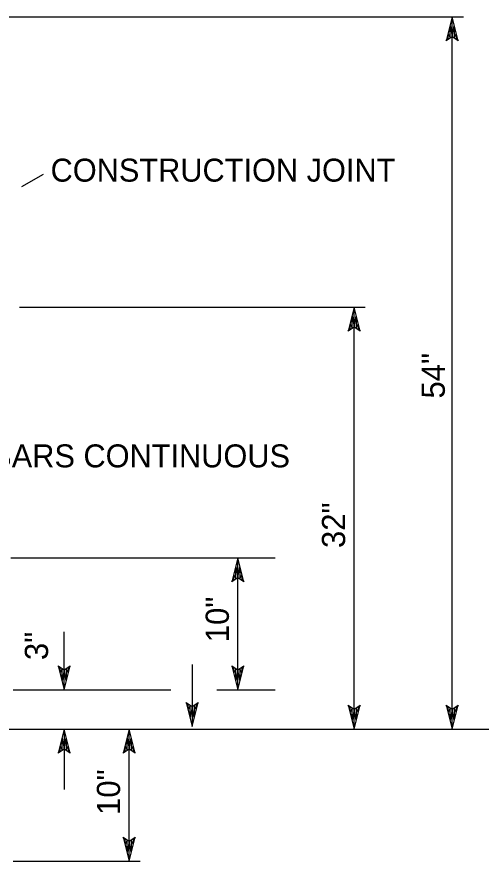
# Model space of a CAD drawing. Extents: x 504255 to 505955, y 659986 to 661086.
# Drawn here: x 504576.9 to 504692.9, y 660124.5 to 660335.2 of the extents above; entities that cross this region are included whole.
import ezdxf

# ---------------------------------------------------------------- set-up
doc = ezdxf.new("R2010")
doc.units = 0
doc.layers.add('Level1', color=7, linetype='Continuous')
doc.layers.add('Level63', color=7, linetype='Continuous')

msp = doc.modelspace()

# ---------------------------------------------------------------- linework, layer by layer
at = {"layer": 'Level1'}
for p, q in [((504537.11, 660335.21), (504688.45, 660335.21)), ((504685.66, 660157.45), (504685.66, 660335.21)), ((504578.14, 660292.9), (504583.59, 660296)), ((504577.6, 660262.79), (504663.96, 660262.79)), ((504661.17, 660157.45), (504661.17, 660262.79)), ((504575.42, 660200.24), (504641.43, 660200.24)), ((504632.14, 660167.32), (504632.14, 660200.24)), ((504588.77, 660167.32), (504588.77, 660181.78)), ((504620.73, 660173.59), (504620.73, 660158.09)), ((504576.05, 660167.32), (504615.42, 660167.32)), ((504626.9, 660167.32), (504641.43, 660167.32)), ((504588.77, 660157.45), (504588.77, 660142.43)), ((504604.96, 660124.54), (504604.96, 660157.45)), ((504576.05, 660124.54), (504607.76, 660124.54))]:
    msp.add_line(p, q, dxfattribs=at)
for points in [[(504687.17, 660329.23), (504685.66, 660335.21), (504684.15, 660329.23), (504684.66, 660329.94), (504684.66, 660330.97), (504685.16, 660329.97), (504685.16, 660332.96), (504685.66, 660330.3), (504686.16, 660332.96), (504686.16, 660329.97), (504686.66, 660330.97), (504686.66, 660329.94), (504687.17, 660329.23), (504685.66, 660330.22), (504684.15, 660329.23)], [(504662.67, 660256.82), (504661.17, 660262.79), (504659.66, 660256.82), (504660.16, 660257.52), (504660.16, 660258.56), (504660.66, 660257.56), (504660.66, 660260.55), (504661.17, 660257.89), (504661.67, 660260.55), (504661.67, 660257.56), (504662.17, 660258.56), (504662.17, 660257.52), (504662.67, 660256.82), (504661.17, 660257.81), (504659.66, 660256.82)], [(504633.65, 660194.26), (504632.14, 660200.24), (504630.64, 660194.26), (504631.14, 660194.97), (504631.14, 660196), (504631.64, 660195), (504631.64, 660197.99), (504632.14, 660195.34), (504632.65, 660197.99), (504632.65, 660195), (504633.15, 660196), (504633.15, 660194.97), (504633.65, 660194.26), (504632.14, 660195.26), (504630.64, 660194.26)], [(504587.26, 660173.31), (504588.77, 660167.32), (504590.28, 660173.31), (504589.78, 660172.6), (504589.78, 660171.57), (504589.27, 660172.56), (504589.27, 660169.58), (504588.77, 660172.24), (504588.26, 660169.58), (504588.26, 660172.56), (504587.76, 660171.57), (504587.76, 660172.6), (504587.26, 660173.31), (504588.77, 660172.31), (504590.28, 660173.31)], [(504630.64, 660173.3), (504632.14, 660167.32), (504633.65, 660173.3), (504633.15, 660172.59), (504633.15, 660171.56), (504632.65, 660172.56), (504632.65, 660169.57), (504632.14, 660172.23), (504631.64, 660169.57), (504631.64, 660172.56), (504631.14, 660171.56), (504631.14, 660172.59), (504630.64, 660173.3), (504632.14, 660172.3), (504633.65, 660173.3)], [(504619.22, 660164.08), (504620.73, 660158.09), (504622.24, 660164.08), (504621.74, 660163.37), (504621.74, 660162.34), (504621.23, 660163.33), (504621.23, 660160.35), (504620.73, 660163), (504620.23, 660160.35), (504620.23, 660163.33), (504619.73, 660162.34), (504619.73, 660163.37), (504619.22, 660164.08), (504620.73, 660163.08), (504622.24, 660164.08)], [(504659.66, 660163.43), (504661.17, 660157.45), (504662.68, 660163.43), (504662.17, 660162.72), (504662.17, 660161.69), (504661.67, 660162.69), (504661.67, 660159.7), (504661.17, 660162.35), (504660.66, 660159.7), (504660.66, 660162.69), (504660.16, 660161.69), (504660.16, 660162.72), (504659.66, 660163.43), (504661.17, 660162.43), (504662.68, 660163.43)], [(504684.15, 660163.43), (504685.66, 660157.45), (504687.17, 660163.43), (504686.66, 660162.72), (504686.66, 660161.69), (504686.16, 660162.69), (504686.16, 660159.7), (504685.66, 660162.35), (504685.15, 660159.7), (504685.15, 660162.69), (504684.65, 660161.69), (504684.65, 660162.72), (504684.15, 660163.43), (504685.66, 660162.43), (504687.17, 660163.43)], [(504590.28, 660151.47), (504588.77, 660157.45), (504587.26, 660151.47), (504587.76, 660152.18), (504587.76, 660153.21), (504588.26, 660152.21), (504588.26, 660155.2), (504588.77, 660152.55), (504589.27, 660155.2), (504589.27, 660152.21), (504589.78, 660153.21), (504589.78, 660152.18), (504590.28, 660151.47), (504588.77, 660152.47), (504587.26, 660151.47)], [(504606.47, 660151.47), (504604.96, 660157.45), (504603.46, 660151.47), (504603.96, 660152.18), (504603.96, 660153.21), (504604.46, 660152.21), (504604.46, 660155.2), (504604.96, 660152.55), (504605.47, 660155.2), (504605.47, 660152.21), (504605.97, 660153.21), (504605.97, 660152.18), (504606.47, 660151.47), (504604.96, 660152.47), (504603.46, 660151.47)], [(504603.46, 660130.51), (504604.96, 660124.54), (504606.47, 660130.51), (504605.97, 660129.8), (504605.97, 660128.78), (504605.47, 660129.78), (504605.47, 660126.78), (504604.96, 660129.44), (504604.46, 660126.78), (504604.46, 660129.78), (504603.96, 660128.78), (504603.96, 660129.8), (504603.46, 660130.51), (504604.96, 660129.51), (504606.47, 660130.51)]]:
    msp.add_lwpolyline(points, dxfattribs=at)
for points in [[(504632.14, 660192.32), (504632.14, 660192.32), (504632.14, 660192.32)], [(504664.78, 660157.45), (504664.78, 660157.45), (504664.78, 660157.45)]]:
    msp.add_lwpolyline(points, close=True, dxfattribs=at)
at = {"layer": 'Level63'}
msp.add_line((504571.81, 660157.45), (504801.61, 660157.45), dxfattribs=at)

# ---------------------------------------------------------------- texts
at = {"layer": 'Level1'}
for s, p in [('CONSTRUCTION JOINT', (504585.36, 660294.09)), ('#4 BARS CONTINUOUS', (504559.87, 660222.79))]:
    msp.add_text(s, height=5.7392, dxfattribs=at).set_placement(p)
for s, p in [('54"', (504683.83, 660239.97)), ('32"', (504658.93, 660202.66)), ('10"', (504629.89, 660179.16)), ('3"', (504584.72, 660174.7)), ('10"', (504602.71, 660136.05))]:
    msp.add_text(s, height=5.797, rotation=90, dxfattribs=at).set_placement(p)

doc.saveas('drawing.dxf')
